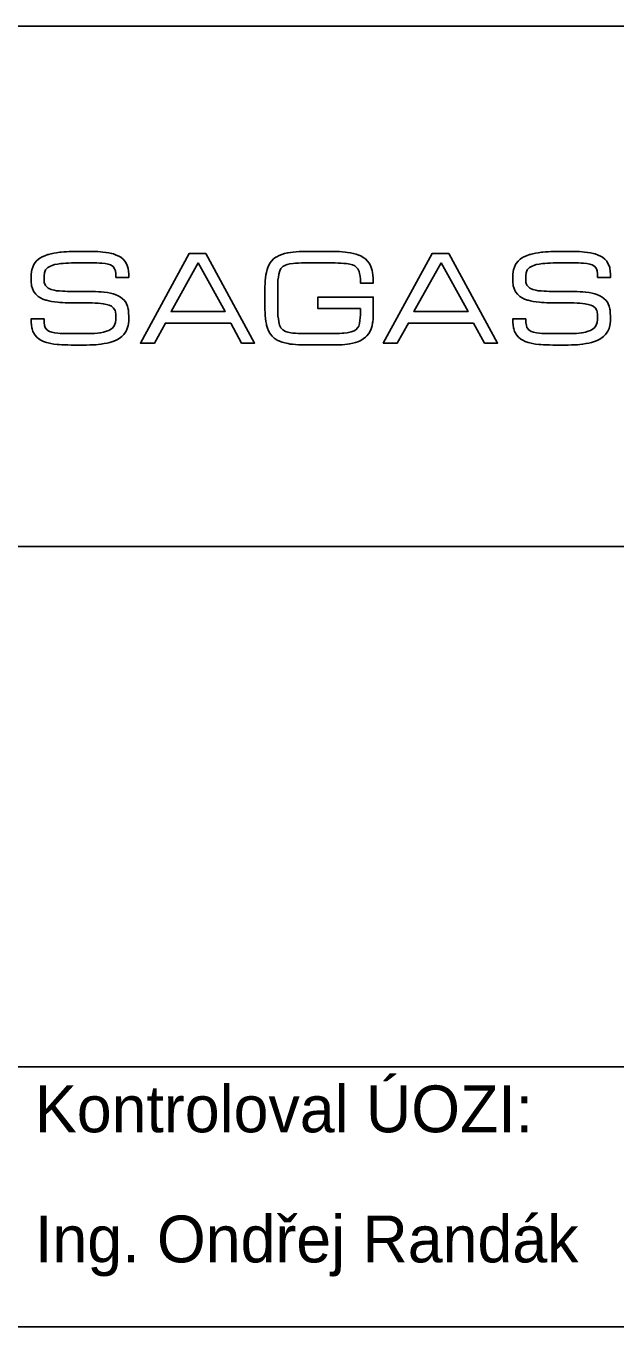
# Model space of a CAD drawing. Extents: x -820819 to -820609, y -1070301 to -1070004.
# Drawn here: x -820667.9 to -820645.2, y -1070198.5 to -1070148.5 of the extents above; entities that cross this region are included whole.
import ezdxf

# ---------------------------------------------------------------- set-up
doc = ezdxf.new("R2010")
doc.units = 0
doc.layers.add('Popisove_pole', color=7, linetype='Continuous')
doc.layers.add('Vrstva 63', color=7, linetype='Continuous')

# ---------------------------------------------------------------- blocks, each defined once
blk = doc.blocks.new('sagasta-logo')
at = {"layer": 'Popisove_pole'}
for points in [[(-0.604, -0.144), (-0.605, -0.121), (-0.607, -0.098), (-0.608, -0.09), (-0.613, -0.068), (-0.622, -0.048), (-0.625, -0.042), (-0.637, -0.023), (-0.654, -0.007), (-0.667, 0.003), (-0.686, 0.013), (-0.709, 0.023), (-0.724, 0.027), (-0.745, 0.032), (-0.767, 0.037), (-0.792, 0.04), (-0.796, 0.04), (-0.816, 0.042), (-0.837, 0.044), (-0.859, 0.045), (-0.883, 0.046), (-0.908, 0.046), (-1.02, 0.046), (-1.025, 0.046), (-1.051, 0.046), (-1.074, 0.046), (-1.095, 0.047), (-1.114, 0.048), (-1.136, 0.05), (-1.158, 0.052), (-1.178, 0.056), (-1.201, 0.062), (-1.224, 0.072), (-1.244, 0.091), (-1.253, 0.115), (-1.254, 0.129), (-1.255, 0.152), (-1.255, 0.165), (-1.251, 0.188), (-1.243, 0.211), (-1.226, 0.229), (-1.205, 0.241), (-1.193, 0.246), (-1.174, 0.252), (-1.151, 0.256), (-1.125, 0.26), (-1.108, 0.262), (-1.088, 0.263), (-1.067, 0.264), (-1.043, 0.265), (-1.019, 0.266), (-0.993, 0.266), (-0.911, 0.266), (-0.897, 0.266), (-0.872, 0.266), (-0.849, 0.265), (-0.829, 0.264), (-0.81, 0.263), (-0.785, 0.26), (-0.763, 0.256), (-0.745, 0.25), (-0.725, 0.237), (-0.713, 0.22), (-0.707, 0.204), (-0.704, 0.182), (-0.703, 0.154), (-0.604, 0.154), (-0.604, 0.179), (-0.606, 0.202), (-0.609, 0.222), (-0.61, 0.23), (-0.618, 0.252), (-0.628, 0.271), (-0.633, 0.278), (-0.647, 0.294), (-0.665, 0.309), (-0.68, 0.317), (-0.7, 0.326), (-0.722, 0.334), (-0.736, 0.338), (-0.757, 0.342), (-0.779, 0.346), (-0.803, 0.349), (-0.82, 0.35), (-0.842, 0.352), (-0.864, 0.353), (-0.887, 0.353), (-0.911, 0.354), (-0.993, 0.354), (-1.014, 0.354), (-1.038, 0.353), (-1.061, 0.352), (-1.083, 0.351), (-1.103, 0.35), (-1.123, 0.348), (-1.134, 0.347), (-1.158, 0.344), (-1.18, 0.34), (-1.201, 0.336), (-1.22, 0.33), (-1.226, 0.329), (-1.249, 0.321), (-1.269, 0.312), (-1.286, 0.302), (-1.298, 0.294), (-1.314, 0.278), (-1.328, 0.262), (-1.333, 0.254), (-1.342, 0.234), (-1.349, 0.212), (-1.351, 0.199), (-1.354, 0.176), (-1.354, 0.152), (-1.354, 0.141), (-1.353, 0.118), (-1.351, 0.096), (-1.35, 0.09), (-1.344, 0.068), (-1.335, 0.048), (-1.331, 0.041), (-1.318, 0.024), (-1.3, 0.008), (-1.283, -0.002), (-1.263, -0.012), (-1.24, -0.02), (-1.237, -0.021), (-1.218, -0.026), (-1.197, -0.03), (-1.174, -0.033), (-1.149, -0.036), (-1.134, -0.038), (-1.114, -0.04), (-1.092, -0.041), (-1.069, -0.042), (-1.045, -0.042), (-1.02, -0.042), (-0.908, -0.042), (-0.885, -0.042), (-0.861, -0.043), (-0.838, -0.044), (-0.818, -0.046), (-0.8, -0.048), (-0.776, -0.053), (-0.754, -0.059), (-0.737, -0.067), (-0.72, -0.082), (-0.709, -0.101), (-0.707, -0.11), (-0.704, -0.131), (-0.703, -0.156), (-0.703, -0.17), (-0.706, -0.193), (-0.715, -0.217), (-0.73, -0.236), (-0.749, -0.25), (-0.756, -0.253), (-0.775, -0.26), (-0.797, -0.266), (-0.822, -0.271), (-0.826, -0.272), (-0.845, -0.274), (-0.866, -0.276), (-0.888, -0.277), (-0.912, -0.278), (-0.938, -0.278), (-1.047, -0.278), (-1.063, -0.278), (-1.088, -0.278), (-1.11, -0.277), (-1.131, -0.276), (-1.149, -0.275), (-1.172, -0.273), (-1.194, -0.268), (-1.213, -0.262), (-1.232, -0.249), (-1.245, -0.231), (-1.25, -0.215), (-1.254, -0.193), (-1.255, -0.165), (-1.354, -0.165), (-1.353, -0.191), (-1.352, -0.214), (-1.349, -0.233), (-1.347, -0.241), (-1.34, -0.263), (-1.329, -0.282), (-1.325, -0.288), (-1.311, -0.305), (-1.293, -0.32), (-1.279, -0.329), (-1.258, -0.338), (-1.236, -0.346), (-1.223, -0.35), (-1.202, -0.354), (-1.179, -0.358), (-1.155, -0.361), (-1.138, -0.362), (-1.118, -0.364), (-1.095, -0.365), (-1.072, -0.365), (-1.047, -0.366), (-0.938, -0.366), (-0.928, -0.366), (-0.904, -0.365), (-0.881, -0.364), (-0.858, -0.363), (-0.838, -0.362), (-0.818, -0.36), (-0.792, -0.355), (-0.77, -0.351), (-0.749, -0.346), (-0.727, -0.339), (-0.705, -0.331), (-0.685, -0.321), (-0.668, -0.309), (-0.658, -0.301), (-0.642, -0.285), (-0.629, -0.268), (-0.624, -0.259), (-0.615, -0.238), (-0.609, -0.216), (-0.607, -0.202), (-0.604, -0.18), (-0.604, -0.156), (-0.604, -0.144)], [(-0.012, 0.339), (-0.139, 0.339), (-0.515, -0.351), (-0.406, -0.351), (-0.322, -0.197), (0.179, -0.197), (0.263, -0.351), (0.363, -0.351), (-0.012, 0.339)], [(0.556, 0.205), (0.565, 0.223), (0.579, 0.238), (0.599, 0.249), (0.612, 0.254), (0.633, 0.259), (0.658, 0.262), (0.659, 0.262), (0.678, 0.263), (0.7, 0.264), (0.723, 0.265), (0.748, 0.265), (0.967, 0.265), (0.981, 0.265), (1.005, 0.264), (1.028, 0.263), (1.049, 0.262), (1.067, 0.26), (1.069, 0.26), (1.093, 0.256), (1.114, 0.25), (1.132, 0.242), (1.14, 0.236), (1.155, 0.22), (1.165, 0.199), (1.169, 0.184), (1.173, 0.164), (1.175, 0.139), (1.175, 0.111), (1.274, 0.111), (1.274, 0.125), (1.274, 0.149), (1.272, 0.172), (1.269, 0.191), (1.266, 0.208), (1.259, 0.23), (1.25, 0.25), (1.243, 0.263), (1.23, 0.28), (1.214, 0.296), (1.197, 0.308), (1.178, 0.319), (1.156, 0.328), (1.142, 0.333), (1.121, 0.338), (1.099, 0.343), (1.075, 0.346), (1.058, 0.349), (1.036, 0.35), (1.014, 0.352), (0.991, 0.353), (0.967, 0.353), (0.748, 0.353), (0.729, 0.353), (0.704, 0.352), (0.681, 0.351), (0.66, 0.349), (0.639, 0.346), (0.621, 0.343), (0.617, 0.343), (0.593, 0.337), (0.572, 0.33), (0.552, 0.323), (0.534, 0.313), (0.527, 0.309), (0.508, 0.296), (0.493, 0.28), (0.48, 0.263), (0.476, 0.257), (0.466, 0.237), (0.458, 0.216), (0.453, 0.192), (0.449, 0.173), (0.446, 0.151), (0.444, 0.128), (0.443, 0.103), (0.442, 0.087), (0.442, 0.065), (0.441, 0.042), (0.441, 0.019), (0.441, -0.006), (0.441, -0.025), (0.441, -0.049), (0.442, -0.072), (0.442, -0.094), (0.443, -0.115), (0.444, -0.139), (0.446, -0.162), (0.449, -0.184), (0.453, -0.205), (0.454, -0.213), (0.461, -0.235), (0.469, -0.256), (0.48, -0.275), (0.484, -0.282), (0.498, -0.298), (0.514, -0.313), (0.537, -0.328), (0.554, -0.336), (0.574, -0.344), (0.596, -0.35), (0.62, -0.355), (0.635, -0.358), (0.655, -0.36), (0.676, -0.362), (0.699, -0.364), (0.723, -0.365), (0.748, -0.365), (0.967, -0.365), (0.989, -0.365), (1.013, -0.364), (1.035, -0.363), (1.056, -0.361), (1.076, -0.359), (1.093, -0.356), (1.116, -0.352), (1.137, -0.346), (1.156, -0.34), (1.178, -0.33), (1.197, -0.319), (1.214, -0.306), (1.225, -0.295), (1.239, -0.278), (1.25, -0.258), (1.258, -0.24), (1.265, -0.219), (1.269, -0.195), (1.27, -0.187), (1.273, -0.166), (1.274, -0.142), (1.274, -0.118), (1.274, 0.003), (0.849, 0.003), (0.849, -0.085), (1.175, -0.085), (1.175, -0.118), (1.175, -0.133), (1.174, -0.157), (1.172, -0.178), (1.169, -0.2), (1.162, -0.22), (1.156, -0.231), (1.141, -0.248), (1.127, -0.257), (1.105, -0.265), (1.094, -0.268), (1.073, -0.272), (1.049, -0.274), (1.036, -0.275), (1.015, -0.276), (0.992, -0.277), (0.967, -0.277), (0.748, -0.277), (0.746, -0.277), (0.72, -0.277), (0.697, -0.276), (0.676, -0.275), (0.657, -0.274), (0.641, -0.272), (0.618, -0.267), (0.6, -0.261), (0.58, -0.25), (0.564, -0.234), (0.554, -0.212), (0.548, -0.187), (0.545, -0.165), (0.542, -0.142), (0.541, -0.117), (0.541, -0.102), (0.541, -0.081), (0.541, -0.058), (0.54, -0.033), (0.54, -0.006), (0.54, 0.018), (0.541, 0.043), (0.541, 0.066), (0.541, 0.087), (0.541, 0.105), (0.541, 0.108), (0.542, 0.133), (0.545, 0.156), (0.548, 0.179), (0.556, 0.205)], [(1.854, 0.339), (1.727, 0.339), (1.351, -0.351), (1.459, -0.351), (1.544, -0.197), (2.044, -0.197), (2.129, -0.351), (2.229, -0.351), (1.854, 0.339)], [(2.458, 0.089), (2.455, 0.094), (2.447, 0.115), (2.446, 0.129), (2.445, 0.152), (2.445, 0.165), (2.449, 0.188), (2.457, 0.211), (2.474, 0.229), (2.495, 0.241), (2.507, 0.246), (2.526, 0.252), (2.549, 0.256), (2.575, 0.26), (2.592, 0.262), (2.612, 0.263), (2.634, 0.264), (2.657, 0.265), (2.681, 0.266), (2.707, 0.266), (2.789, 0.266), (2.803, 0.266), (2.828, 0.266), (2.851, 0.265), (2.871, 0.264), (2.89, 0.263), (2.915, 0.26), (2.937, 0.256), (2.955, 0.25), (2.975, 0.237), (2.988, 0.22), (2.993, 0.204), (2.996, 0.182), (2.997, 0.154), (3.097, 0.154), (3.096, 0.179), (3.094, 0.202), (3.091, 0.222), (3.09, 0.23), (3.082, 0.252), (3.072, 0.271), (3.067, 0.278), (3.053, 0.294), (3.035, 0.309), (3.02, 0.317), (3.001, 0.326), (2.978, 0.334), (2.964, 0.338), (2.943, 0.342), (2.921, 0.346), (2.897, 0.349), (2.88, 0.35), (2.859, 0.352), (2.837, 0.353), (2.813, 0.353), (2.789, 0.354), (2.707, 0.354), (2.686, 0.354), (2.662, 0.353), (2.639, 0.352), (2.617, 0.351), (2.597, 0.35), (2.577, 0.348), (2.566, 0.347), (2.542, 0.344), (2.52, 0.34), (2.499, 0.336), (2.48, 0.33), (2.474, 0.329), (2.452, 0.321), (2.431, 0.312), (2.414, 0.302), (2.402, 0.294), (2.386, 0.278), (2.372, 0.262), (2.367, 0.254), (2.358, 0.234), (2.351, 0.212), (2.349, 0.199), (2.346, 0.176), (2.346, 0.152), (2.346, 0.141), (2.347, 0.118), (2.349, 0.096), (2.35, 0.09), (2.356, 0.068), (2.365, 0.048), (2.369, 0.041), (2.382, 0.024), (2.4, 0.008), (2.417, -0.002), (2.437, -0.012), (2.46, -0.02), (2.463, -0.021), (2.482, -0.026), (2.503, -0.03), (2.526, -0.033), (2.551, -0.036), (2.566, -0.038), (2.587, -0.04), (2.608, -0.041), (2.631, -0.042), (2.655, -0.042), (2.68, -0.042), (2.792, -0.042), (2.815, -0.042), (2.84, -0.043), (2.862, -0.044), (2.882, -0.046), (2.9, -0.048), (2.925, -0.053), (2.946, -0.059), (2.963, -0.067), (2.98, -0.082), (2.991, -0.101), (2.993, -0.11), (2.996, -0.131), (2.997, -0.156), (2.997, -0.17), (2.994, -0.193), (2.985, -0.217), (2.97, -0.236), (2.951, -0.25), (2.944, -0.253), (2.926, -0.26), (2.904, -0.266), (2.878, -0.271), (2.874, -0.272), (2.855, -0.274), (2.834, -0.276), (2.812, -0.277), (2.788, -0.278), (2.762, -0.278), (2.653, -0.278), (2.637, -0.278), (2.612, -0.278), (2.59, -0.277), (2.569, -0.276), (2.551, -0.275), (2.528, -0.273), (2.506, -0.268), (2.488, -0.262), (2.468, -0.249), (2.455, -0.231), (2.45, -0.215), (2.446, -0.193), (2.445, -0.165), (2.346, -0.165), (2.347, -0.191), (2.348, -0.214), (2.351, -0.233), (2.353, -0.241), (2.36, -0.263), (2.371, -0.282), (2.375, -0.288), (2.389, -0.305), (2.407, -0.32), (2.422, -0.329), (2.442, -0.338), (2.464, -0.346), (2.478, -0.35), (2.498, -0.354), (2.521, -0.358), (2.545, -0.361), (2.562, -0.362), (2.583, -0.364), (2.605, -0.365), (2.628, -0.365), (2.653, -0.366), (2.762, -0.366), (2.772, -0.366), (2.797, -0.365), (2.82, -0.364), (2.842, -0.363), (2.862, -0.362), (2.882, -0.36), (2.884, -0.359), (2.908, -0.355), (2.93, -0.351), (2.951, -0.346), (2.974, -0.339), (2.995, -0.331), (3.015, -0.321), (3.032, -0.309), (3.043, -0.301), (3.058, -0.285), (3.071, -0.268), (3.076, -0.259), (3.085, -0.238), (3.091, -0.216), (3.093, -0.202), (3.096, -0.18), (3.097, -0.156), (3.096, -0.144), (3.095, -0.121), (3.093, -0.098), (3.092, -0.09), (3.087, -0.068), (3.078, -0.048), (3.075, -0.042), (3.063, -0.023), (3.046, -0.007), (3.033, 0.003), (3.014, 0.013), (2.991, 0.023), (2.976, 0.027), (2.955, 0.032), (2.933, 0.037), (2.908, 0.04), (2.904, 0.04), (2.884, 0.042), (2.863, 0.044), (2.841, 0.045), (2.817, 0.046), (2.792, 0.046), (2.68, 0.046), (2.675, 0.046), (2.649, 0.046), (2.626, 0.046), (2.605, 0.047), (2.587, 0.048), (2.564, 0.05), (2.542, 0.052), (2.522, 0.056), (2.499, 0.062), (2.476, 0.072), (2.458, 0.089)], [(-0.071, 0.266), (0.136, -0.109), (-0.279, -0.109), (-0.071, 0.266)], [(1.795, 0.266), (2.002, -0.109), (1.586, -0.109), (1.795, 0.266)]]:
    blk.add_lwpolyline(points, dxfattribs=at)

msp = doc.modelspace()

# ---------------------------------------------------------------- linework, layer by layer
at = {"layer": 'Popisove_pole'}
for p, q in [((-820799.096, -1070168.524), (-820629.096, -1070168.524)), ((-820799.096, -1070188.524), (-820629.096, -1070188.524))]:
    msp.add_line(p, q, dxfattribs=at)
msp.add_lwpolyline([(-820799.096, -1070148.524), (-820629.096, -1070148.524), (-820629.096, -1070198.524), (-820799.096, -1070198.524)], close=True, dxfattribs=at)

# ---------------------------------------------------------------- block references
at = {"layer": 'Popisove_pole', "xscale": 4.999999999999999, "yscale": 4.999999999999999, "rotation": -1.310668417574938e-10}
msp.add_blockref('sagasta-logo', (-820660.898, -1070158.956), dxfattribs=at)

# ---------------------------------------------------------------- texts
at = {"layer": 'Vrstva 63'}
for s, p in [('Kontroloval ÚOZI:', (-820667.518, -1070191.042)), ('Ing. Ondřej Randák', (-820667.518, -1070196.042))]:
    msp.add_text(s, height=1.8, dxfattribs=at).set_placement(p)

doc.saveas('drawing.dxf')
